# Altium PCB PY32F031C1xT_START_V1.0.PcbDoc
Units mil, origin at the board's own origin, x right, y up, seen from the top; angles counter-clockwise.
Board outline 2400.05 x 1600.05 mil, 2 copper layers (Top Layer, Bottom Layer); 34 components, 55 nets, 183 pads, 129 vias.
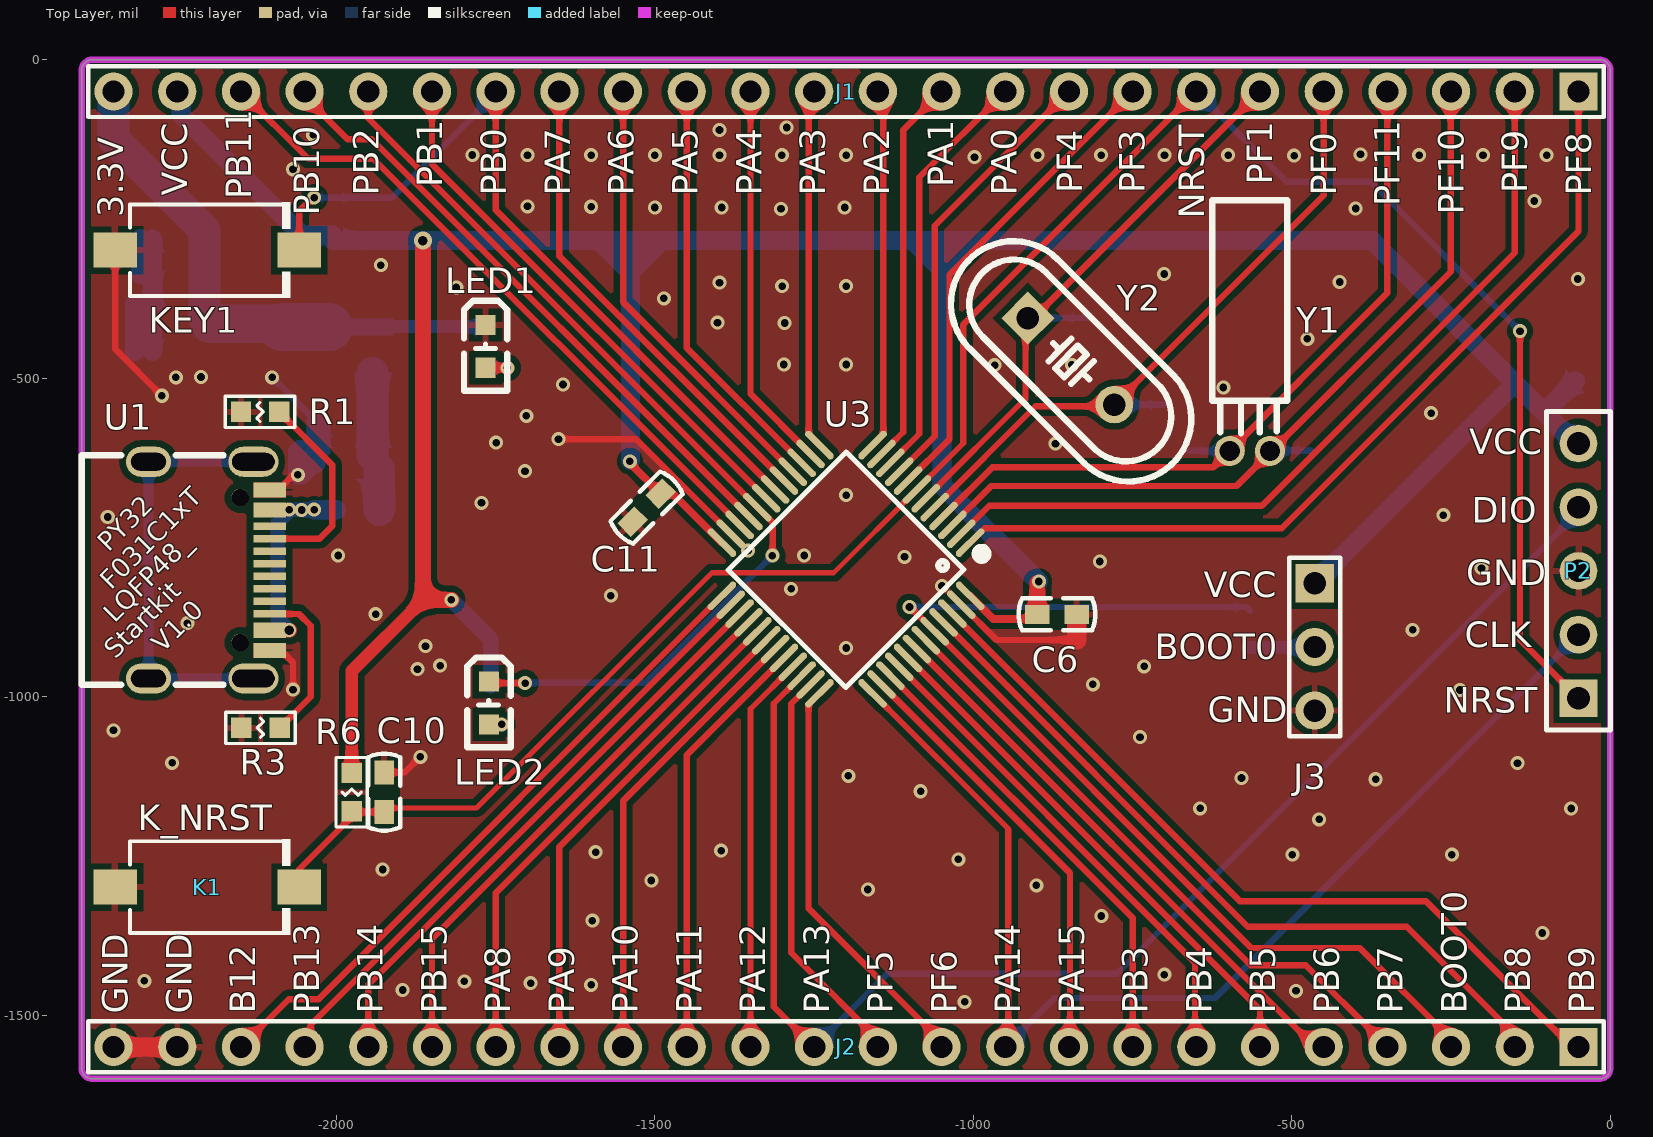
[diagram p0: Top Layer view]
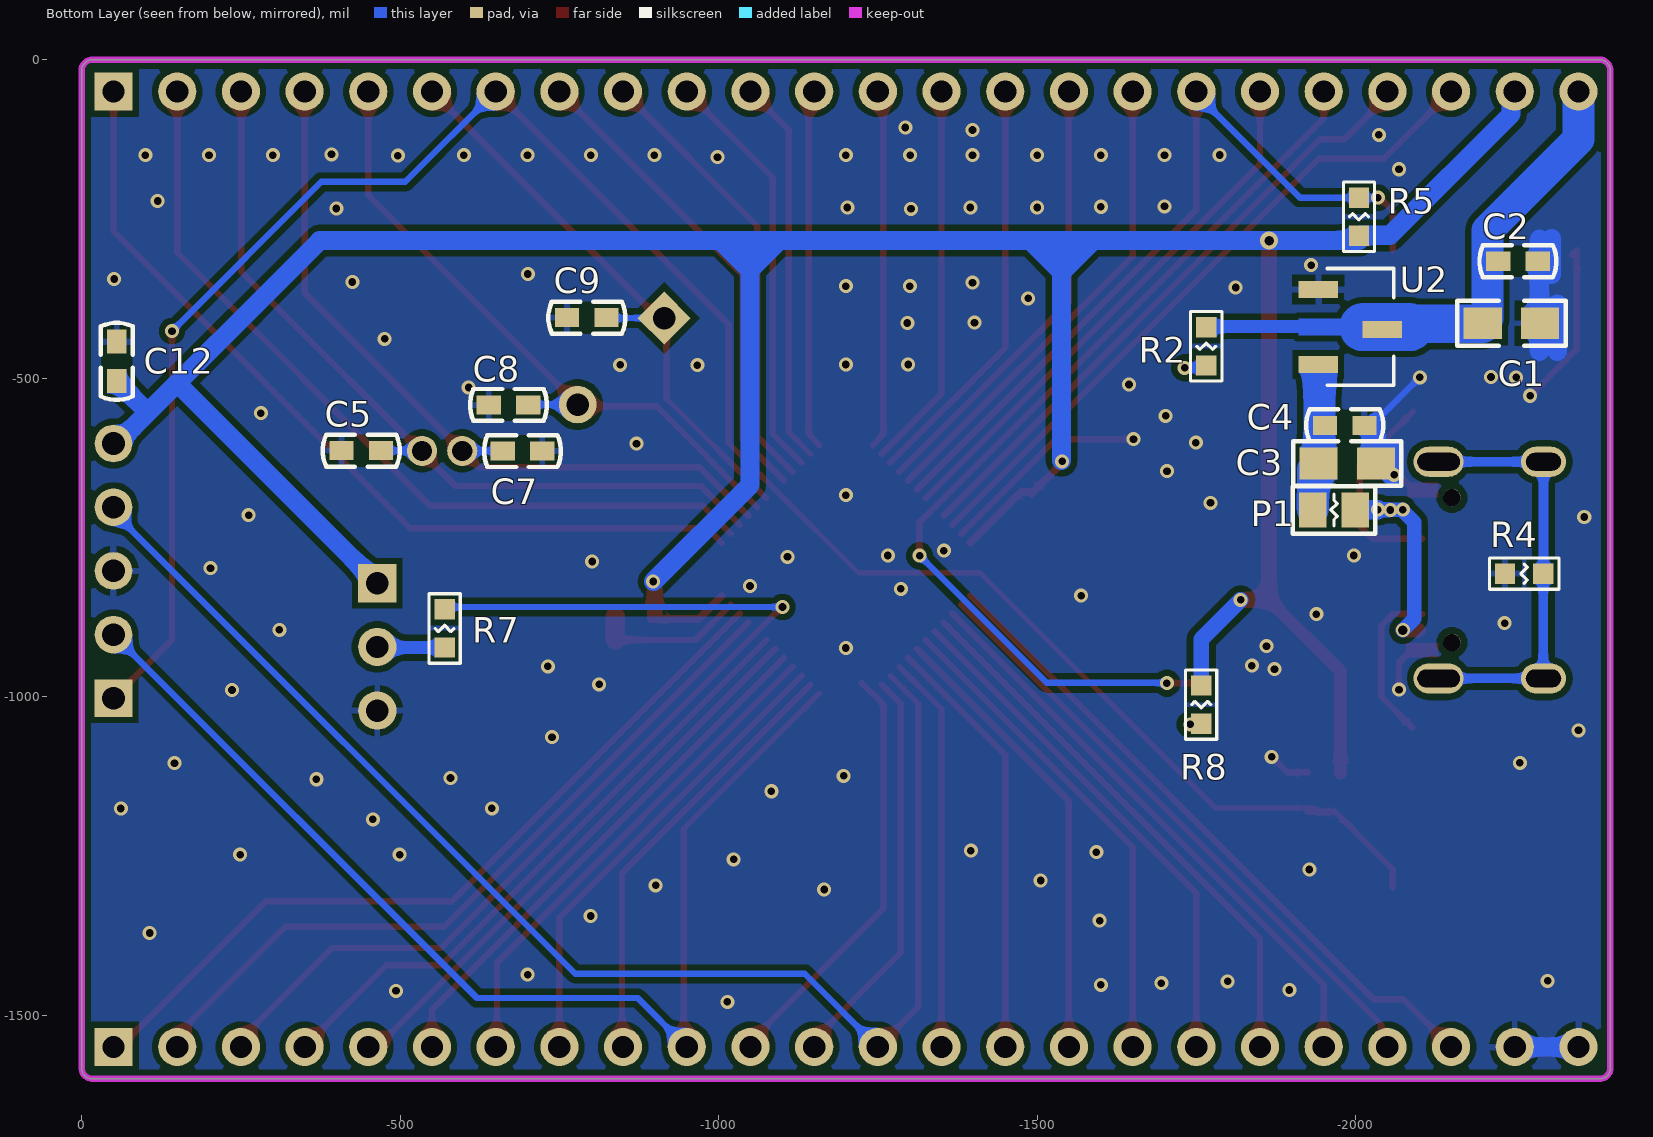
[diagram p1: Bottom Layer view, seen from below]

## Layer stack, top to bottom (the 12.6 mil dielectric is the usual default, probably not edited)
Top Solder: solder mask 0.4, Solder Resist, Dk 3.5
Top Layer: signal copper 1.4
Dielectric1: core 12.6, FR-4, Dk 4.8
Bottom Layer: signal copper 1.4
Bottom Solder: solder mask 0.4, Solder Resist, Dk 3.5

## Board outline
-2400,-1581.74 ccw(c-2383.22,-1583.22) -2384.71,-1600 -18.26,-1600 ccw(c-16.78,-1583.22) 0,-1584.71 0,-18.26 ccw(c-16.78,-16.78) -15.29,0 -2384.71,0 -2381.74,0 ccw(c-2383.22,-16.78) -2400,-15.29 -2400,-14.79

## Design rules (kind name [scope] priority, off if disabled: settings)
Clearance [All] p1: gap=10 ignorepadtopadclearanceinfootprint=FALSE
ComponentClearance [All] p1: gap=0 collisioncheckmode=3 verticalgap=0 showdistances=FALSE
DiffPairsRouting [All] p1: maxlimit=50 minlimit=1 mostfreqgap=1 toplayer_minwidth=15 toplayer_maxwidth=15 toplayer_prefwidth=15 bottomlayer_minwidth=15 bottomlayer_maxwidth=15 bottomlayer_prefwidth=15 maxuncoupledlength=500
HoleSize [All] p1: absolutevalues=TRUE maxlimit=9999 minlimit=1 maxpercent=80.000 minpercent=20.000
HoleToHoleClearance [All] p1: gap=1 allowstackedmicrovias=TRUE
MinimumSolderMaskSliver [All] p1: minsoldermaskwidth=0
PlaneConnect [All] p1: planeconnectstyle=Direct reliefexpansion=20 reliefentries=4 reliefconductorwidth=10 reliefairgap=10
PolygonConnect PolygonConnect_1 [IsVia] p1: connectstyle=Direct reliefconductorwidth=10 reliefentries=4 polygonreliefangle="90 Angle" airgapwidth=10
PolygonConnect [All] p2: connectstyle=Relief reliefconductorwidth=10 reliefentries=4 polygonreliefangle="90 Angle" airgapwidth=10
RoutingCorners [All] p1: cornerstyle=45-Degree minsetback=30 maxsetback=1000
RoutingVias [All] p1: holewidth=28 width=50 viastyle="Through Hole" minholewidth=1 minwidth=1 maxholewidth=10000 maxwidth=10000
SilkToSilkClearance [All] p1: silktosilkclearance=0
SilkToSolderMaskClearance [IsPad] p1: minsilkscreentomaskgap=0 clearancetoexposedcopper=TRUE
SolderMaskExpansion [All] p1: expansion=4 istentingtop=FALSE
Width [InNetClass('NET')] p1: maxlimit=1000 minlimit=5 preferedwidth=9 checkconnectedcopper=TRUE
21 further rules are at their usual default settings.

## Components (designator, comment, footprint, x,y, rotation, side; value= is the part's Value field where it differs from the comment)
C1 "10uF" C0805 -2244.68,-413.83 r0 bottom
C2 "100nF" C0603 -2254.93,-316.47 r0 bottom
C3 "10uF" C0805 -1986.94,-634.12 r0 bottom
C4 "100nF" C0603 -1983.03,-574.16 r0 bottom
C5 "22pF" C0603 -438.87,-613.81 r0 bottom
C6 "100nF" C0603 -868.7,-870.84 r0 top
C7 "22pF" C0603 -692.01,-614.53 r180 bottom
C8 "22pF" C0603 -670.12,-542.03 r0 bottom
C9 "22pF" C0603 -793.15,-404.98 r0 bottom
C10 "100nF" C0603 -1925,-1150 r270 top
C11 "100nF" C0603 -1513.1,-703.22 r45 top
C12 "100nF" C0603 -55.03,-473.59 r270 bottom
J1 "CON24" CON24 -50,-50 r180 top locked
J2 "CON24" CON24 -50,-1550 r180 top locked
J3 "CON3" CON3 -464.14,-821.96 r270 top
K1 "1TS002B-2600-5001_key" SW -2250,-1300 r0 top
KEY1 "1TS002B-2600-5001" SW -2250,-300 r0 top locked
LED1 "RED" 0603_LED -1766.72,-464.7 r270 top
LED2 "GREEN" 0603_LED -1761.6,-1024.58 r270 top
P1 "SMD1210P005TF" R0805 -1966.2,-706.92 r0 bottom
P2 "Debug" HDR1X5 -50,-1002.64 r90 top locked
R1 "5.1K" R0603 -2119.96,-553.02 r0 top
R2 "510" R0603 -1765.63,-450.09 r90 bottom
R3 "5.1K" R0603 -2119.32,-1049.08 r180 top
R4 "1M" R0603 -2264.68,-806.96 r0 bottom
R5 "1.5K" R0603 -2005.35,-246.71 r270 bottom
R6 "10K" R0603 -1976.09,-1150 r90 top
R7 "10K" R0603 -569.75,-892.97 r90 bottom
R8 "680R" R0603 -1757.72,-1012.55 r270 bottom
U1 "KH-TYPE-C-16P" USB-C-SMD_KH-TYPE-C-16P -2200,-801.33 r270 top locked
U2 "LM1117-3.3" LM1117-3.3 -1941.56,-360.55 r0 bottom
U3 "PY32F031C1xT" LQFP-48_L7.0-W7.0-P0.50-LS9.0-BL -1200,-800 r135 top
Y1 "32.768KHz" 32768KHZ_2 -570.09,-490.46 r270 top value=X503225MSB2GI
Y2 "24M" 25MHZ_2 -825,-500 r315 top locked value=X503225MSB2GI

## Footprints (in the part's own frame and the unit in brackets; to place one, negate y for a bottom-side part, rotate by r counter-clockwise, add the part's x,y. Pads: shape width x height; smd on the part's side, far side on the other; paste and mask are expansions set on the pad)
25MHZ_2 [mm]
  rect 1.5x1.5 hole 0.9: 1(-3.302,0.087)
  round 1.5 hole 0.9: 2(1.578,0.087)
  silkscreen extent -6.6,-2.41 4.88,2.59
0603_LED [mil]
  rect 31.5x31.5 smd: 1(19,1) 2(-48,1)
  silkscreen extent -86,-33 55,35
32768KHZ_2 [mm]
  round 1.2 hole 0.8: 1(3.142,0.903) 2(3.142,-0.697)
  silkscreen extent -6.86,-1.4 2.44,1.6
C0603 [mil]
  rect 38x30 smd: 1(-31,0) 2(31,0)
  silkscreen extent -60,-25 60,25
C0805 [mil]
  rect 60x50 smd: 1(-45,0) 2(45,0)
  silkscreen extent -85,-35 85,35
CON3 [mil]
  rect 60x60 hole 35: 1(0,0)
  round 60 hole 35: 2(100,0) 3(200,0)
  silkscreen extent -40,-40 240,40
CON24 [mil]
  rect 60x60 hole 35: 1(0,0)
  round 60 hole 35: 2(100,0) 3(200,0) 4(300,0) 5(400,0) 6(500,0) 7(600,0) 8(700,0) 9(800,0) 10(900,0) 11(1000,0) 12(1100,0) 13(1200,0) 14(1300,0) 15(1400,0) 16(1500,0) 17(1600,0) 18(1700,0) 19(1800,0) 20(1900,0) 21(2000,0) 22(2100,0) 23(2200,0) 24(2300,0)
  silkscreen extent -40,-40 2340,40
HDR1X5 [mm] "Connector; Header; 5 Position"
  rect 1.5x1.5 hole 0.9: 1(0,0)
  round 1.5 hole 0.9: 2(2.54,0) 3(5.08,0) 4(7.62,0) 5(10.16,0)
  silkscreen extent -1.27,-1.27 11.43,1.27
LM1117-3.3 [mm]
  rect 1.575x0.672 smd: 1(0,0) 2(-2.55,1.598) 3(0,3)
  Top Layer region: -3.64,2.459 -1.785,2.459 -1.741,2.458 -1.696,2.455 -1.652,2.449 -1.608,2.442 -1.565,2.433 -1.522,2.421 -1.479,2.408 -1.437,2.393 -1.396,2.375 -1.356,2.356 -1.317,2.335 -1.279,2.312 -1.241,2.288 -1.206,2.261 -1.171,2.233 -1.138,2.204 -1.106,2.173 -1.075,2.14 -1.047,2.106 -1.019,2.071 -0.994,2.034 -0.97,1.996 -0.948,1.958 -0.928,1.918 -0.91,1.839 0.788,1.839 0.788,1.179 -0.91,1.179 -0.928,1.099 -0.948,1.06 -0.97,1.021 -0.994,0.983 -1.019,0.947 -1.047,0.911 -1.075,0.877 -1.106,0.845 -1.138,0.814 -1.171,0.784 -1.206,0.756 -1.241,0.73 -1.279,0.705 -1.317,0.682 -1.356,0.661 -1.396,0.642 -1.437,0.625 -1.479,0.609 -1.522,0.596 -1.565,0.585 -1.608,0.575 -1.652,0.568 -1.696,0.563 -1.741,0.56 -1.785,0.559 -3.64,0.559 -3.684,0.56 -3.728,0.563 -3.773,0.568 -3.817,0.575 -3.86,0.585 -3.903,0.596 -3.946,0.609 -3.988,0.625 -4.029,0.642 -4.069,0.661 -4.108,0.682 -4.146,0.705 -4.183,0.73 -4.219,0.756 -4.254,0.784 -4.287,0.814 -4.319,0.845 -4.349,0.877 -4.378,0.911 -4.405,0.947 -4.431,0.983 -4.455,1.021 -4.477,1.06 -4.497,1.099 -4.515,1.14 -4.531,1.181 -4.546,1.224 -4.558,1.266 -4.568,1.31 -4.577,1.353 -4.583,1.398 -4.587,1.442 -4.589,1.486 -4.589,1.531 -4.587,1.575 -4.583,1.62 -4.577,1.664 -4.568,1.708 -4.558,1.751 -4.546,1.794 -4.531,1.836 -4.515,1.877 -4.497,1.918 -4.477,1.958 -4.455,1.996 -4.431,2.034 -4.405,2.071 -4.378,2.106 -4.349,2.14 -4.319,2.173 -4.287,2.204 -4.254,2.233 -4.219,2.261 -4.183,2.288 -4.146,2.312 -4.108,2.335 -4.069,2.356 -4.029,2.375 -3.988,2.393 -3.946,2.408 -3.903,2.421 -3.86,2.433 -3.817,2.442 -3.773,2.449 -3.728,2.455 -3.684,2.458
  silkscreen extent -3.01,-0.83 -0.35,3.83
LQFP-48_L7.0-W7.0-P0.50-LS9.0-BL [mm]
  oval 0.27x1.5 smd mask+0.05: 1(-2.75,-4.25) 2(-2.25,-4.25) 3(-1.75,-4.25) 4(-1.25,-4.25) 5(-0.75,-4.25) 6(-0.25,-4.25) 7(0.25,-4.25) 8(0.75,-4.25) 9(1.25,-4.25) 10(1.75,-4.25) 11(2.25,-4.25) 12(2.75,-4.25) 25(2.75,4.25) 26(2.25,4.25) 27(1.75,4.25) 28(1.25,4.25) 29(0.75,4.25) 30(0.25,4.25) 31(-0.25,4.25) 32(-0.75,4.25) 33(-1.25,4.25) 34(-1.75,4.25) 35(-2.25,4.25) 36(-2.75,4.25)
  oval 1.5x0.27 smd mask+0.05: 13(4.25,-2.75) 14(4.25,-2.25) 15(4.25,-1.75) 16(4.25,-1.25) 17(4.25,-0.75) 18(4.25,-0.25) 19(4.25,0.25) 20(4.25,0.75) 21(4.25,1.25) 22(4.25,1.75) 23(4.25,2.25) 24(4.25,2.75) 37(-4.25,2.75) 38(-4.25,2.25) 39(-4.25,1.75) 40(-4.25,1.25) 41(-4.25,0.75) 42(-4.25,0.25) 43(-4.25,-0.25) 44(-4.25,-0.75) 45(-4.25,-1.25) 46(-4.25,-1.75) 47(-4.25,-2.25) 48(-4.25,-2.75)
  silkscreen extent -3.59,-4.46 3.3,3.34
R0603 [mil]
  rect 32x32 smd: 1(-30,0) 2(30,0)
  silkscreen extent -55,-24 54,25
R0805 [mm]
  rect 1.1x1.4 smd: 1(-0.85,0) 2(0.85,0)
  silkscreen extent -1.65,-0.95 1.65,0.95
SW [mm]
  rect 1.74x1.4 smd: 1(-2.476,0.024) 2(4.864,0.024)
  silkscreen extent -1.88,-1.88 4.5,1.93
USB-C-SMD_KH-TYPE-C-16P [mm]
  oval 1.2x2 hole 0.7 slot 1.7 at 90 deg: 1(-4.32,1.765) 2(4.32,1.765)
  oval 1.2x1.8 hole 0.7 slot 1.4 at 90 deg: 3(-4.32,-2.415) 4(4.32,-2.415)
  rect 0.3x1.3 smd: A1(-3.35,2.415) A4(-2.55,2.415) A5(-1.25,2.415) A6(-0.25,2.415) A7(0.25,2.415) A8(1.25,2.415) A9(2.55,2.415) A12(3.35,2.415) B1(3.05,2.415) B4(2.25,2.415) B5(1.75,2.415) B6(0.75,2.415) B7(-0.75,2.415) B8(-1.75,2.415) B9(-2.25,2.415) B12(-3.05,2.415)
  round 0.7 hole 0.7 unplated: ""(-2.89,1.235) ""(2.89,1.235)
  silkscreen extent -4.57,-5.08 4.57,0.57

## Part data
C1 C3: library part C0805
C2 C4 C5 C6 C7 C8 C9 C10 C11 C12: library part C0603
K1: BOM_JLCPCB Part Class="Extended Part", BOM_Manufacturer=HYP, BOM_Manufacturer Part=1TS002B-2600-5001_KEY
KEY1: BOM_JLCPCB Part Class="Extended Part", BOM_Manufacturer=HYP
LED1 LED2: library part PDI-E803_Dup1
P2: library part CON5
R1 R2 R3 R4 R5 R6 R7 R8: library part R0603
U1: BOM_JLCPCB Part Class="Extended Part", BOM_Manufacturer="Shenzhen Kinghelm Elec"
U3: "LQFP48"
Y1: library part CRYSTAL_1, "Crystal"
Y2: library part CRYSTAL, "Crystal"

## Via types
v1: diameter 22, hole 12, Top Layer to Bottom Layer, 122 vias
v2: diameter 22, hole 12, Top Layer to Bottom Layer, tented both sides, 5 vias
v3: diameter 28, hole 15, Top Layer to Bottom Layer, 1 vias
v4: diameter 22, hole 15, Top Layer to Bottom Layer, tented both sides, 1 vias

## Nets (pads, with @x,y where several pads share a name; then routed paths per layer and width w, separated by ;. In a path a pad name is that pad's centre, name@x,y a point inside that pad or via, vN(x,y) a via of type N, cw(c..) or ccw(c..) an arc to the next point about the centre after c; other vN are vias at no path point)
BOOT0: J2.3 R7.2 U3.44 | length 1667
  Top Layer w10: v1@-1098.88,-859.36 U3.44 -563.5,-1394.74 -393.12,-1394.74 J2.3@-250,-1537.86
  Bottom Layer w10: v1(-1100.41,-859.36) -571.45,-859.36 R7.2@-565.73,-865.08
GND: C1.1 C2.1 C3.1 C4.1 C5.2 C6.2 C7.2 C8.2 C9.2 C10.1 C11.1 C12.1 J2.23 J2.24 J3.3 K1.1 KEY1.1 LED1.2 P2.3 R1.1 R3.2 R4.2 U1.A1 U1.A12 U1.B1 U1.B12 U2.1 U3.23 U3.47 | length 1950.1
  Top Layer w10: KEY1.1@-2339.79,-306.73 KEY1.1 -2347.48,-454.24 v1(-2274.09,-527.64) ; U1.A12 U1.A12@-2090.75,-933.22 ; U1.B1 -2102.56,-921.41 U1.A12@-2090.75,-933.22 ; U1.A1 -2085.23,-669.44 -2069.86,-654.06 -2062.99,-654.06 v1(-2060.69,-651.77) ; v1(-2068.28,-989.1) -2068.28,-946.43 -2081.5,-933.22 U1.A12@-2090.75,-933.22 ; C10.1 -1892.99,-1119 v1(-1868.42,-1094.43) ; v1(-1651.43,-595.76) -1529.51,-595.76 U3.23 ; U3.47 -963.66,-911.07 -837.79,-911.07
  Top Layer w30: J2.24@-2350.92,-1550.31 J2.24@-2348.11,-1550.31 ; J2.24@-2348.11,-1562.28 J2.24@-2348.11,-1550.31 ; J2.23@-2250.73,-1564.8 J2.23@-2250.73,-1550.31 ; J2.23@-2242.15,-1550.31 J2.23@-2250.73,-1550.31 ; -837.79,-911.07 C6.2@-837.79,-874.3 ; J2.24@-2348.11,-1550.31 J2.23@-2250.73,-1550.31
  Bottom Layer w10: C2.1 -2285.93,-283.62 ; v1(-2100.96,-498.84) -2035.65,-564.16 C4.1@-2028.03,-564.16 ; C4.1@-2028.02,-564.17 C4.1@-2025.65,-566.54 ; C3.1@-2014.03,-616.21 C4.1 C4.1@-2018.03,-574.16 ; P2.3@-64.55,-802.64 P2.3 ; C4.1@-2025.65,-566.54 C4.1@-2018.03,-574.16 ; C4.1@-2025.65,-566.54 -2025.65,-574.16 C4.1@-2018.03,-574.16
  Bottom Layer w30: J2.24 J2.23 ; -2316.65,-457.81 -2316.65,-383.85 ; -2307.6,-337.32 -2307.6,-281.02 ; -2288.72,-458.29 -2288.72,-281.23 ; C3.1@-2057.69,-612.09 -2060.69,-615.1 v1(-2060.69,-651.77) -2054.59,-651.77 -2036.94,-634.12 C3.1 ; C3.1@-2031.87,-610.79 C4.1@-2031.87,-568.02
  other v1: -1013.59,-1479.11 -493.42,-1461.93 -1896.1,-1460.58 -1600,-1452.56 -1695,-1450 -1799.33,-1446.95 -2301.64,-1446.29 -700.23,-1436.56 -106.68,-1371.24 -1598.19,-1351.68 -799.18,-1344.45 -1165.76,-1302.89 -901.06,-1296.21 -1505.49,-1288.6 -1927.36,-1271.54 -1023.51,-1255.39 -499.34,-1248.22 -248.93,-1248.22 -1593.04,-1244.12 -1396,-1241.92 -457.15,-1192.56 -643.85,-1175.52 -61.54,-1175.68 -1082.76,-1148.57 -368.29,-1129.73 -578.97,-1127.82 -1196.28,-1124.28 -145.7,-1104.6 -2257.89,-1104 -738.42,-1063.77 -2350,-1052.91 -236.04,-989.72 -812.58,-980.74 -1872.76,-956.98 -731.75,-952.35 -1837.19,-951.35 -1199.65,-923.75 -1860.22,-920.67 -310.3,-895.3 -2234.05,-884.62 -1938.46,-870.45 -1569.22,-841.62 -1286.13,-830.86 -1049.3,-826.31 -202.23,-798.25 -801.59,-787.88 -1108.08,-780.56 -1997.34,-778.43 -1265.56,-778.43 -1353.53,-770.77 -2359.08,-718.02 -262.26,-714.97 -1772.25,-695.74 -1199.65,-683.77 -1703.92,-645.95 -871.13,-602.93 -1749.2,-601.37 -1701.96,-559.09 -281.33,-554.98 -607.49,-514.68 -1644.31,-510.06 -2252.09,-498.84 -2212.62,-498.26 -966.52,-479.66 -1297.46,-478.6 -1199.65,-478.6 -845.36,-478.97 -475.75,-438.27 -1401.83,-412.97 -1296.39,-413.37 -1485.96,-374.72 -1811.66,-357.66 -1300.12,-355.55 -1199.65,-355.55 -1398.63,-350 -425,-348.97 -50.89,-344.36 -700.56,-336.39 -1930.36,-322.67 -1302.03,-234.08 -399.7,-233.65 -1500,-232.14 -1395.29,-232.14 -1202.22,-232.14 -1600,-230.9 -1700,-230.22 -119.16,-221.8 -2068.28,-172.02 -998.17,-153.01 -496.47,-150.8 -1786.74,-149.71 -1700,-150 -1600,-150 -1500,-150 -1398.63,-150 -1300.65,-150 -1199.65,-150 -899.14,-150 -799.43,-150 -700,-150 -600,-150 -300,-150 -200,-150 -100,-150 -392.26,-148.62 -2036.7,-118.08 -1398.63,-110.38 -1293.18,-106.47
NetC3_2: C3.2 C4.2 P1.2 U2.3 | length 225.8
  Bottom Layer w25: C3.2@-1952.03,-624.03 C3.2 C3.2@-1932.74,-643.33
  Bottom Layer w50: C3.2@-1943.37,-620.6 C4.2@-1943.37,-570.73 ; C4.2@-1943.33,-576.64 U2.3@-1943.33,-491.62 ; P1.2 C3.2@-1932.74,-643.33
NetJ3_2: J3.2 R7.1 | length 104.6
  Bottom Layer w20: R7.1 J3.2@-465.14,-922.97
NetLED1_1: LED1.1 R2.1 | length 69.4
  Top Layer w15: LED1.1 v1(-1731.72,-483.7)
  Bottom Layer w15: R2.1 -1762.02,-483.7 v1(-1731.72,-483.7)
NetLED2_1: LED2.1 R8.2 | length 37.6
  Top Layer w10: LED2.1 v1(-1740.55,-1043.58)
  Bottom Layer w10: R8.2 -1741.58,-1042.55 v1(-1740.55,-1043.58)
NetR1_2: R1.2 U1.A5 | length 320.2
  Top Layer w10: U1.A5 -2026.69,-752.12 -2006.61,-732.03 -2006.61,-636.38 R1.2
NetR3_1: R3.1 U1.B5 | length 252.9
  Top Layer w10: U1.B5 -2058.8,-870.23 -2040.4,-888.63 -2040.4,-1000.16 R3.1
NetR4_1: R4.1 U1.1 U1.2 U1.3 U1.4 | length 669.6
  Bottom Layer w15: U1.2 U1.4 -2294.68,-971.01 R4.1 -2295.08,-806.56 U1.3 U1.1
NRST: C10.2 J1.7 K1.2 P2.1 R6.1 U3.7 | length 3336.8
  Top Layer w8: C10.2@-1934.47,-1175 -1780,-1175 -1410.5,-805.5 -1219.41,-805.5 U3.7 -1015.69,-601.77
  Top Layer w10: K1.2 -2058.5,-1271.1 -1968.4,-1181 C10.2 ; -1015.69,-601.77 -1015.69,-415.69 J1.7 ; v2(-141.7,-426.11) -141.7,-910.94 P2.1
  Bottom Layer w10: J1.7 -508.11,-191.89 -375.92,-191.89 v2(-141.7,-426.11)
OSC32_IN: C5.1 J1.3 U3.3 Y1.1 | length 1295.1
  Top Layer w10: U3.3 -971.89,-669.33 -586.85,-669.33 -250.74,-333.22 -250.74,-50.74 J1.3
  Bottom Layer w10: Y1.1 -534.2,-613.81 C5.1
OSC32_OUT: C7.1 J1.4 U3.4 Y1.2 | length 1221.9
  Top Layer w10: U3.4 -970.58,-640.17 -623.82,-640.17 -350,-366.35 J1.4
  Bottom Layer w10: C7.1 -660.64,-614.16 Y1.2
OSC_IN: C8.1 J1.5 U3.5 Y2.2 | length 1054.3
  Top Layer w9: U3.5 -902.46,-544.22
  Top Layer w10: -902.46,-544.22 -781.34,-544.22 Y2.2 -450,-212.88 J1.5
  Bottom Layer w10: Y2.2 -701.62,-541.52 C8.1
OSC_OUT: C9.1 J1.6 U3.6 Y2.1 | length 984.6
  Top Layer w9: U3.6 -918.24,-532.16
  Top Layer w10: Y2.1@-927.59,-427.59 J1.6 ; -918.24,-532.16 -918.24,-409.41 Y2.1
  Bottom Layer w10: Y2.1 C9.1@-819.72,-405.66 ; C9.1@-827.37,-405.2 C9.1@-822.82,-400.65
PA0: J1.10 U3.10 | length 657.7
  Top Layer w9: U3.10 -1084.75,-587.32
  Top Layer w10: -1084.75,-587.32 -1084.75,-184.75 J1.10
PA1: J1.11 U3.11 | length 608.1
  Top Layer w9: U3.11 -1110.34,-585.06
  Top Layer w10: -1110.34,-585.06 -1110.34,-110.34 J1.11
PA2: J1.12 U3.12 | length 565.8
  Top Layer w10: U3.12 -1141.24,-588.13 -1141.24,-58.76 J1.12
PA3: J1.13 U3.13 | length 565.8
  Top Layer w10: J1.13 -1258.75,-58.76 -1258.75,-588.13 U3.13
PA4: J1.14 U3.14 | length 608.1
  Top Layer w10: J1.14 -1350,-524.73 U3.14
PA5: J1.15 U3.15 | length 657.7
  Top Layer w10: J1.15 -1450,-452.56 U3.15
PA6: J1.16 U3.16 | length 707.3
  Top Layer w10: J1.16 -1550,-380.41 U3.16
PA7: J1.17 U3.17 | length 756.8
  Top Layer w10: J1.17 -1650,-308.24 U3.17
PA8: J2.18 U3.29 | length 822.7
  Top Layer w10: J2.18 -1750,-1308.24 U3.29
PA9: J2.17 U3.30 | length 781.6
  Top Layer w10: J2.17@-1661.81,-1531.12 J2.17@-1655.86,-1525.18 ; J2.17 -1650,-1236.08 U3.30
PA10: J2.16 U3.31 | length 723.6
  Top Layer w10: J2.16 -1550,-1163.92 U3.31
PA11: J2.15 U3.32 | length 674
  Top Layer w10: J2.15 -1450,-1091.76 U3.32
PA12: J2.14 U3.33 | length 624.4
  Top Layer w9: -1350,-1019.59 U3.33
  Top Layer w10: J2.14 -1350,-1019.59
PA13: J2.13 P2.4 U3.34 | length 2182.9
  Top Layer w9: -1313.32,-1010.76 U3.34
  Top Layer w10: -1313.32,-1010.76 -1313.32,-1486.68 J2.13
  Bottom Layer w10: J2.13 -1135.37,-1435.37 -774.95,-1435.37 -50,-710.42 P2.4
PA14: J2.10 P2.2 U3.37 | length 1810.7
  Top Layer w9: U3.37 -945.1,-1208.02 -945.1,-1208.73
  Top Layer w10: J2.10 -945.1,-1545.1 -945.1,-1208.73
  Bottom Layer w10: J2.10@-947.87,-1548.14 -872.99,-1473.26 -620.62,-1473.26 P2.2
PA15: J2.9 U3.38 | length 690
  Top Layer w10: U3.38 -848.41,-1276.86 J2.9@-848.41,-1548.41
PB0: J1.18 KEY1.2 R5.1 U3.18 | length 1256.8
  Top Layer w10: KEY1.2 -2058.5,-236.94 -2051.43,-229.87 -2051.29,-229.87 -2038.14,-216.71 v2(-2034.89,-216.71) ; J1.18 -1750,-236.08 U3.18
  Bottom Layer w10: v2(-2034.89,-216.71) R5.1 -1912.76,-216.71 -1750,-53.95 J1.18
PB1: J1.19 U3.19 | length 856
  Top Layer w10: J1.19 -1850,-163.92 U3.19
PB2: J1.20 LED2.2 U3.20 | length 1521.5
  Top Layer w10: J1.20 -1950,-91.76 U3.20 -1315.24,-726.53 -1315.24,-778.43 v2(-1315.58,-778.78) ; LED2.2@-1758.31,-978.87 v2(-1703.76,-978.87)
  Bottom Layer w10: v2@-1707.92,-978.47 -1515.27,-978.47 v2(-1315.58,-778.78)
PB3: J2.8 U3.39 | length 740.5
  Top Layer w10: U3.39 -749.86,-1347.58 J2.8@-749.86,-1549.86
PB4: J2.7 U3.40 | length 787.3
  Top Layer w10: U3.40 -651.96,-1417.63 J2.7@-651.96,-1548.04
PB5: J2.6 U3.41 | length 839.7
  Top Layer w10: U3.41 -550,-1491.76 J2.6
PB6: J2.5 U3.42 | length 897.4
  Top Layer w10: U3.42 -473.48,-1540.43 -459.57,-1540.43 J2.5
PB7: J2.4 U3.43 | length 968.9
  Top Layer w10: U3.43 -564.42,-1421.66 -477.9,-1421.66 J2.4@-364.3,-1535.26
PB8: J2.2 U3.45 | length 1184.1
  Top Layer w10: U3.45 -569.15,-1361.26 -319.69,-1361.26 -150,-1530.95 J2.2
PB9: J2.1 U3.46 | length 1263.8
  Top Layer w10: U3.46 -581.38,-1321.18 -289.41,-1321.18 -62.89,-1547.7 J2.1@-50,-1547.7
PB10: J1.21 U3.21 | length 977.5
  Top Layer w10: J1.21 -2050,-57.75 -1982.75,-125 -1944.59,-125 U3.21
PB11: J1.22 U3.22 | length 1064.8
  Top Layer w10: J1.22 -2044.53,-155.47 -1941.97,-155.47 U3.22
PB12: J2.22 U3.25 | length 1048.5
  Top Layer w10: J2.22 -2075,-1475 -2028.12,-1475 U3.25
PB13: J2.21 U3.26 | length 996.7
  Top Layer w10: J2.21@-2050,-1524.73 J2.21 -2040.43,-1540.43 -2040.43,-1515.16 U3.26
PB14: J2.20 U3.27 | length 921.9
  Top Layer w10: J2.20 -1950,-1452.56 U3.27
PB15: J2.19 U3.28 | length 872.3
  Top Layer w10: J2.19 -1850,-1380.41 U3.28
PF3: J1.8 U3.8 | length 756.8
  Top Layer w10: U3.8 -1037.52,-595.76 -1037.52,-337.52 J1.8
PF4: J1.9 U3.9 | length 707.3
  Top Layer w10: U3.9 -1060.91,-591.32 -1060.91,-260.91 J1.9
PF5: J2.12 U3.35 | length 643
  Top Layer w10: U3.35 -1286.13,-1011.4 -1286.13,-1402.16 J2.12@-1138.22,-1550.07
PF6: J2.11 U3.36 | length 647.6
  Top Layer w10: U3.36 -1258.88,-1011.99 -1258.88,-1332.39 J2.11@-1061.18,-1530.09 ; U3.36@-1241.31,-995.32 U3.36@-1224.76,-978.78
PF8: J1.1 U3.1 | length 1377
  Top Layer w10: U3.1 -982.32,-735.44 -516.1,-735.44 -50,-269.33 J1.1
PF9: J1.2 U3.2 | length 1305
  Top Layer w10: U3.2 -974.94,-700.21 -546.98,-700.21 -150,-303.23 J1.2
TYPE_C: P1.1 U1.A4 U1.A9 U1.B4 U1.B9 | length 302.1
  Top Layer w23: U1.A9@-2098.94,-895.91 v4@-2073.56,-895.91
  Bottom Layer w23: v4(-2074.28,-895.63) -2092.23,-877.68 -2092.23,-726.51 v1@-2074.28,-708.56 ; v1(-2074.28,-706.6) -2054.74,-706.6 v1(-2034.89,-706.6)
  Bottom Layer w30: v1(-2034.89,-706.6) -1999.99,-706.6 P1.1
  other v1: -2054.74,-706.92
VCC: C6.1 C11.2 C12.2 J1.23 J3.1 P2.5 R5.2 R6.2 R8.1 U3.24 U3.48 | length 5364.6
  Top Layer w12: v1(-1539.24,-630.61) -1539.24,-633.23 C11.2 -1488.35,-678.47 -1475.62,-678.47 -1472.79,-681.3 -1471.82,-681.3 U3.24 ; U3.48 -968.72,-878.16 C6.1@-911.94,-878.16 ; C6.1@-913.85,-880.08 C6.1@-911.94,-878.16 ; C6.1@-899.7,-877.13 -910.9,-877.13 C6.1@-911.94,-878.16 ; C6.1@-893.51,-878.16 C6.1@-911.94,-878.16
  Top Layer w20: R6.2 -1976.09,-959.83 -1864.37,-848.11
  Top Layer w25: v3(-1864.37,-284.01) -1864.37,-848.11 v1(-1819.71,-848.14) ; C6.1 v2@-899.7,-821.88
  Bottom Layer w25: v1(-1819.71,-848.14) -1757.72,-910.13 -1757.72,-979.05 -1759.43,-980.76 -1759.51,-980.76 R8.1
  Bottom Layer w30: J1.23@-2249.61,-44.73 -2244.26,-50.08 -2244.26,-85.56 -2054.1,-275.71 -2006.35,-275.71 R5.2 R5.2@-2005.35,-277.71 ; R5.2@-2005.35,-284.01 v3(-1864.37,-284.01) -1538.54,-284.01 ; v1@-1538.54,-629.49 -1538.54,-284.01 ; -1049.3,-288.15 -1049.3,-667.88 v2@-897.89,-819.3 ; J3.1 -157.04,-514.87 ; -101.54,-551.1 C12.2 ; P2.5@-55.03,-602.64 -373.65,-284.01 -1538.54,-284.01
  other v2: -897.12,-819.3
VCC_OUT: C1.2 C2.2 J1.24 R2.2 U2.2 | length 780.7
  Bottom Layer w20: -1952.18,-418.83 -1768.83,-418.83 R2.2@-1765.63,-422.03
  Bottom Layer w25: C1.2@-2211.46,-402.06 -2207.09,-406.43 C1.2
  Bottom Layer w50: J1.24 -2350,-125 -2207.09,-267.91 -2207.09,-361.79 C1.2@-2207.09,-406.43
  Bottom Layer w60: C1.2@-2198.82,-414.7 -2050.69,-414.7 U2.2
pads on no net: U1. U1.A6 U1.A7 U1.A8 U1.B6 U1.B7 U1.B8

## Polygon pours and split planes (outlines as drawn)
GND on Bottom Layer "GND_L02_P002" (solid, remove dead copper, pour order 2): -2400,0 0,0 0,-1600 -2400,-1600
GND on Top Layer "GND_L01_P000" (solid, remove dead copper, pour order 0): -2400,-1.1 -2398.9,0 0,0 0,-1600 -2400,-1600.01

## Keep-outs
Keep-Out Layer:
  lines w10: -2400,-15.29 cw(c-2383.22,-16.78) -2381.74,0 ; -2400,-14.79 -2400,-1581.74 ccw(c-2383.22,-1583.22) -2384.71,-1600 -1712.5,-1600 -337.5,-1600 -18.26,-1600 ccw(c-16.78,-1583.22) 0,-1584.71 0,-18.26 ccw(c-16.78,-16.78) -15.29,0 -2384.71,0

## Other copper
Top Layer:
  rectangle net GND: -2130.32,-687.18 -2081.24,-664
  rectangle net GND: -2130.32,-938.87 -2079.53,-915.88
  rectangle net GND: -2129.74,-938.58 -2081.24,-937.49
  rectangle net GND: -2129.75,-916.6 -2080.55,-916.59
Bottom Layer:
  region net VCC: -1130.42,-269.47 -1048.7,-351.18 -966.99,-269.47
  region net VCC: -1623.14,-269.47 -1538.62,-353.99 -1454.1,-269.47

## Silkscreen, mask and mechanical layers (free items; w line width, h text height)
Top Overlay:
  text "PF1" at -530.86,-196.47 h40 r90
  text "PB1" at -1833.53,-200.49 h40 r90
  text "PA1" at -1031.88,-200.49 h40 r90
  text "PF4" at -828.89,-209.79 h40 r90
  text "PF3" at -731.27,-209.79 h40 r90
  text "PF9" at -130.03,-209.79 h40 r90
  text "VCC" at -2234.35,-213.82 h40 r90
  text "PB2" at -1933.73,-213.82 h40 r90
  text "PB0" at -1733.32,-213.82 h40 r90
  text "PA7" at -1633.11,-213.82 h40 r90
  text "PA6" at -1532.91,-213.82 h40 r90
  text "PA5" at -1432.7,-213.82 h40 r90
  text "PA4" at -1332.5,-213.82 h40 r90
  text "PA3" at -1232.29,-213.82 h40 r90
  text "PA2" at -1132.09,-213.82 h40 r90
  text "PA0" at -931.68,-213.82 h40 r90
  text "PF0" at -430.65,-213.82 h40 r90
  text "PF8" at -29.83,-213.82 h40 r90
  text "PB11" at -2133.49,-219.15 h40 r90
  text "PF11" at -330.45,-229.79 h40 r90
  text "PF10" at -230.24,-243.12 h40 r90
  text "PB10" at -2027.24,-245.21 h40 r90
  text "3.3V" at -2334.55,-247.14 h40 r90
  text "NRST" at -637.51,-249.78 h40 r90
  text "VCC" at -221.65,-619.6 h40
  text "DIO" at -217.24,-726.92 h40
  text "PY32" at -2357.68,-774.37 h30 r45
  text "GND" at -226.5,-825.27 h40
  text "F031C1xT" at -2353.91,-833.63 h30 r45
  text "VCC" at -638.36,-843.92 h40
  text "LQFP48_" at -2348.23,-885.31 h30 r45
  text "CLK" at -228.72,-922.22 h40
  text "V1.0" at -2272.59,-932.59 h30 r45
  text "BOOT0" at -715.21,-941.17 h40
  text "Startkit" at -2347.62,-942.05 h30 r45
  text "NRST" at -261.31,-1025.56 h40
  text "GND" at -632.37,-1040.04 h40
  text "K_NRST" at -2312.06,-1209.72 h40
  text "GND" at -2327.39,-1497.72 h40 r90
  text "GND" at -2227.3,-1497.72 h40 r90
  text "B12" at -2127.21,-1497.72 h40 r90
  text "PB13" at -2027.12,-1497.72 h40 r90
  text "PB14" at -1927.03,-1497.72 h40 r90
  text "PB15" at -1826.94,-1497.72 h40 r90
  text "PA8" at -1726.85,-1497.72 h40 r90
  text "PA9" at -1626.75,-1497.72 h40 r90
  text "PA10" at -1526.66,-1497.72 h40 r90
  text "PA11" at -1426.57,-1497.72 h40 r90
  text "PA12" at -1326.48,-1497.72 h40 r90
  text "PA13" at -1226.39,-1497.72 h40 r90
  text "PF5" at -1126.3,-1497.72 h40 r90
  text "PF6" at -1026.21,-1497.72 h40 r90
  text "PA14" at -926.12,-1497.72 h40 r90
  text "PA15" at -826.02,-1497.72 h40 r90
  text "PB3" at -725.93,-1497.72 h40 r90
  text "PB4" at -625.84,-1497.72 h40 r90
  text "PB5" at -525.75,-1497.72 h40 r90
  text "PB6" at -425.66,-1497.72 h40 r90
  text "PB7" at -325.57,-1497.72 h40 r90
  text "BOOT0" at -225.48,-1497.72 h40 r90
  text "PB8" at -125.39,-1497.72 h40 r90
  text "PB9" at -25.29,-1497.72 h40 r90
